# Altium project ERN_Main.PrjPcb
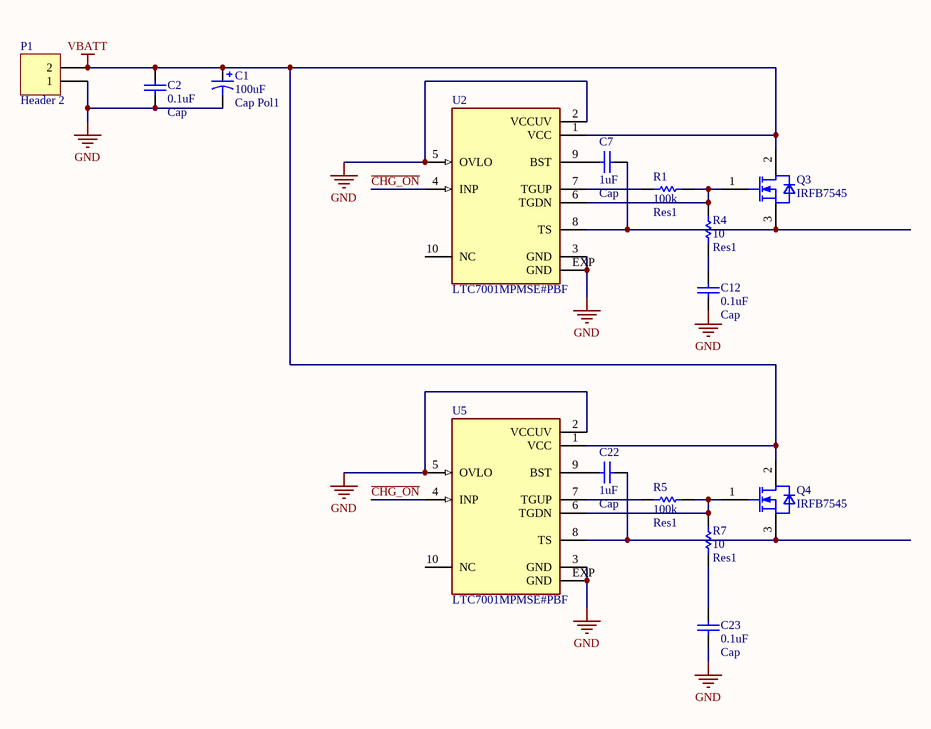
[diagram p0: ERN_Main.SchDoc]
4 sheets, 85 parts. Net scope: global (net labels, ports and power ports of the same name join across sheets).
Sheets:
  ERN_Main.SchDoc
  ERN_Main_2.SchDoc
  ERN_Main_3.SchDoc
  ERN_Main_4.SchDoc

## Sheet ERN_Main.SchDoc
size A; SheetNumber: 1; SheetTotal: 4; SPICEModelCacheDBTNACQE: <root> / <DocumentId>DBTNACQE</DocumentId> / </root>

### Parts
C1  Cap Pol1  value 100uF  [RB7.6-15]
C2  Cap  value 0.1uF  [RAD-0.3]
C7  Cap  value 1uF  [RAD-0.3]
C12  Cap  value 0.1uF  [RAD-0.3]
C22  Cap  value 1uF  [RAD-0.3]
C23  Cap  value 0.1uF  [RAD-0.3]
P1  Header 2  [HDR1X2]
Q3  IRFB7545  [IFX-PG-TO220-3-904]
Q4  IRFB7545  [IFX-PG-TO220-3-904]
R1  Res1  value 100k  [AXIAL-0.3]
R4  Res1  value 10  [AXIAL-0.3]
R5  Res1  value 100k  [AXIAL-0.3]
R7  Res1  value 10  [AXIAL-0.3]
U2  LTC7001MPMSE#PBF  [SOP50P490X110-11N]
U5  LTC7001MPMSE#PBF  [SOP50P490X110-11N]

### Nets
GND: C1.2 C2.1 C12.2 C23.2 P1.1 U2.2(VCCUV) U2.3(GND) U2.5(OVLO) U2.EXP(GND) U5.2(VCCUV) U5.3(GND) U5.5(OVLO) U5.EXP(GND)
VBATT: C1.1 C2.2 P1.2 Q3.2(DRAIN) Q4.2(DRAIN) U2.1(VCC) U5.1(VCC)
~{CHG_ON}: U2.4(INP) U5.4(INP)
NetC7_1: C7.1 Q3.3(SOURCE) U2.8(TS)
NetC7_2: C7.2 U2.9(BST)
NetC12_1: C12.1 R4.2
NetC22_1: C22.1 Q4.3(SOURCE) U5.8(TS)
NetC22_2: C22.2 U5.9(BST)
NetC23_1: C23.1 R7.2
NetQ3_1: Q3.1(GATE) R1.1 R4.1 U2.6(TGDN)
NetQ4_1: Q4.1(GATE) R5.1 R7.1 U5.6(TGDN)
NetR1_2: R1.2 U2.7(TGUP)
NetR5_2: R5.2 U5.7(TGUP)

Not connected (* = marked no-connect by the designer): U2 10(NC); U5 10(NC)

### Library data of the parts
C1 = Cap Pol1: Polarized Capacitor (Radial)
C2 C7 C12 C22 C23 = Cap: Capacitor
P1 = Header 2: Header, 2-Pin
Q3 Q4 = IRFB7545: N-Channel 60V 95A; Insulated-Gate Field-Effect Transistor (IGFET), N-Channel, Enhancement, Body Diode, Pin 1 Gate, 2 Drain, 3 Source, 3 Pins; Manufacturer: Infineon Technologies
R1 R4 R5 R7 = Res1: Resistor
U2 U5 = LTC7001MPMSE#PBF: Fast 150V High Side NMOS Static Switch Driver; MF: Analog Devices

## Sheet ERN_Main_2.SchDoc
size A; SheetNumber: 2; SheetTotal: 4; SPICEModelCacheYVUKJMZF: <root> / <DocumentId>YVUKJMZF</DocumentId> / <CacheFrame Number="0"> / <Model Name="1n5400" Kind="MDL"> / <Text>*1N5400 MCE / * 50V 3A Si Rectifier pkg:DO-201 1,2 / .MODEL 1N5400 D(IS=2.68E-12 RS=0.00977 N=1.17 TT=1.44E-5 CJO=1.24E-10 / + VJ=0.6 M=0.333 BV=66.6 IBV=1E-5 )</Text> / </Model> / <Model Name="led2" Kind="MDL"> / <Text>*Typ RED,GREEN,YELLOW,AMBER GaAs LED: Vf=2.1V Vr=4V If=40mA trr=3uS / *LED Pinout: 1=A, 2=K / .MODEL LED2 D (IS=93.1P RS=42M N=4.61 BV=4 IBV=10U / + CJO=2.97P VJ=.75 M=.333 TT=4.32U)</Text> / </Model> / </CacheFrame> / </root>
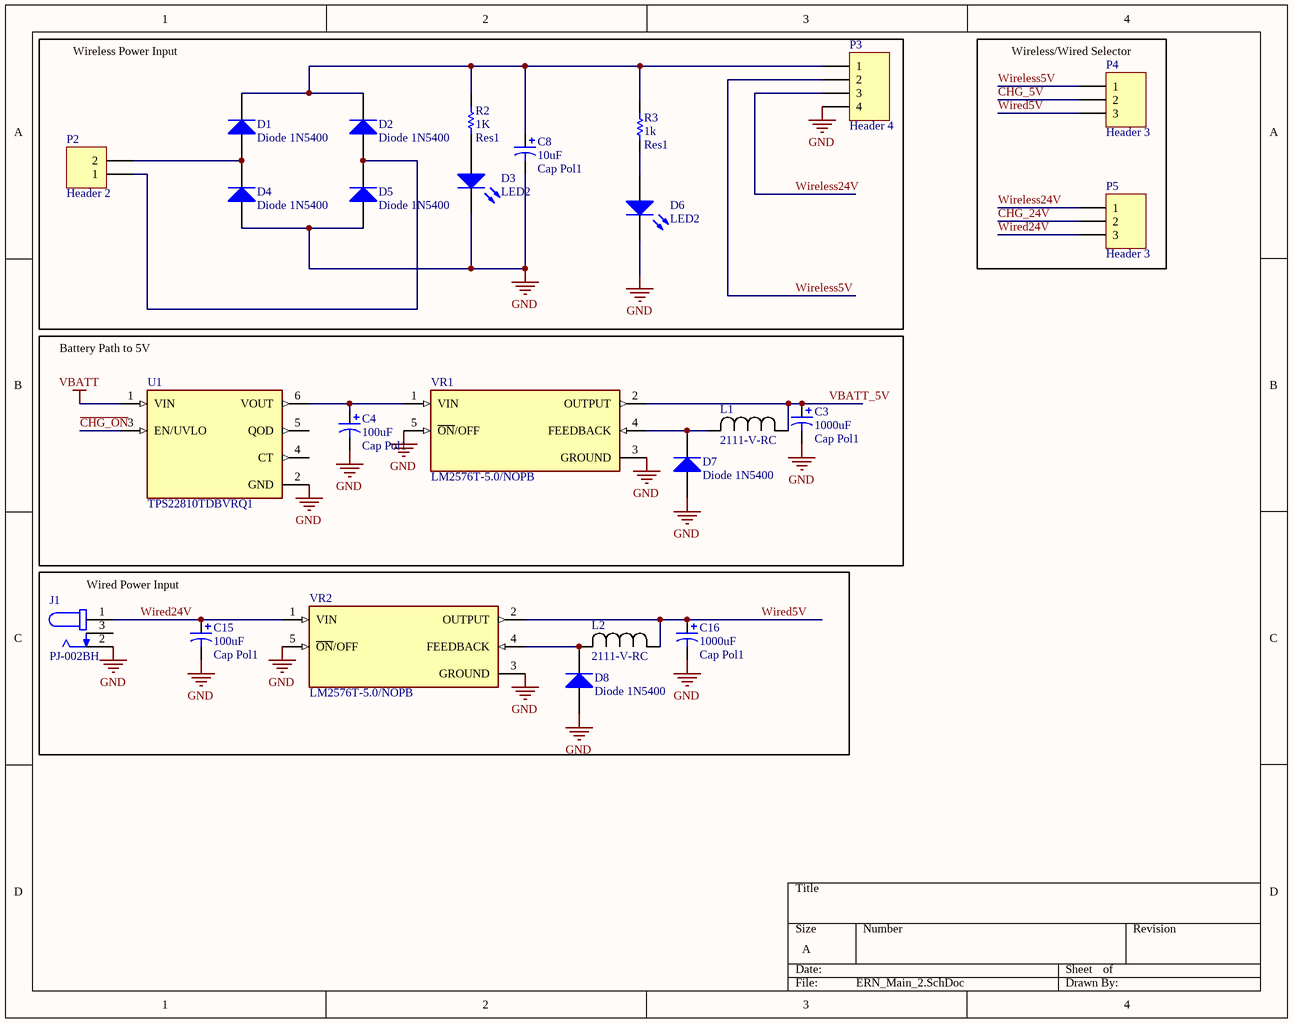
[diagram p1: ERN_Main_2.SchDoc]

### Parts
C3  Cap Pol1  value 1000uF  [RB7.6-15]
C4  Cap Pol1  value 100uF  [RB7.6-15]
C8  Cap Pol1  value 10uF  [RB7.6-15]
C15  Cap Pol1  value 100uF  [RB7.6-15]
C16  Cap Pol1  value 1000uF  [RB7.6-15]
D1  Diode 1N5400  [DO-201AD]
D2  Diode 1N5400  [DO-201AD]
D3  LED2  [3.2X1.6X1.1]
D4  Diode 1N5400  [DO-201AD]
D5  Diode 1N5400  [DO-201AD]
D6  LED2  [3.2X1.6X1.1]
D7  Diode 1N5400  [DO-201AD]
D8  Diode 1N5400  [DO-201AD]
J1  PJ-002BH  [CUI_PJ-002BH]
L1  2111-V-RC  [IND_21XX_27A_V]
L2  2111-V-RC  [IND_21XX_27A_V]
P2  Header 2  [HDR1X2]
P3  Header 4  [HDR1X4]
P4  Header 3  [HDR1X3]
P5  Header 3  [HDR1X3]
R2  Res1  value 1K  [AXIAL-0.3]
R3  Res1  value 1k  [AXIAL-0.3]
U1  TPS22810TDBVRQ1  [SOT95P280X145-6N]
VR1  LM2576T-5.0/NOPB  [TO170P1067X483X1651-5]
VR2  LM2576T-5.0/NOPB  [TO170P1067X483X1651-5]

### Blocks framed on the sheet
Wireless Power Input: C8 D1-D6 P2 P3 R2 R3
Wireless/Wired Selector: P4 P5
Battery Path to 5V: C3 C4 D7 L1 U1 VR1
Wired Power Input: C15 C16 D8 J1 L2 VR2

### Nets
GND: C3.2 C4.2 C8.2 C15.2 C16.2 D3.2(K) D4.1(A) D5.1(A) D6.2(K) D7.1(A) D8.1(A) J1.2 P3.4 U1.2(GND) VR1.3(GROUND) VR1.5(~{ON}/OFF) VR2.3(GROUND) VR2.5(~{ON}/OFF)
VBATT: U1.1(VIN)
~{CHG_ON}: U1.3(EN/UVLO)
CHG_5V: P4.2
CHG_24V: P5.2
VBATT_5V: C3.1 L1.1 VR1.2(OUTPUT)
Wired5V: C16.1 L2.1 P4.3 VR2.2(OUTPUT)
Wired24V: C15.1 J1.1 P5.3 VR2.1(VIN)
Wireless5V: P3.2 P4.1
Wireless24V: P3.3 P5.1
NetC4_1: C4.1 U1.6(VOUT) VR1.1(VIN)
NetC8_1: C8.1 D1.2(K) D2.2(K) P3.1 R2.2 R3.2
NetD1_1: D1.1(A) D4.2(K) P2.2
NetD2_1: D2.1(A) D5.2(K) P2.1
NetD3_1: D3.1(A) R2.1
NetD6_1: D6.1(A) R3.1
NetD7_2: D7.2(K) L1.2 VR1.4(FEEDBACK)
NetD8_2: D8.2(K) L2.2 VR2.4(FEEDBACK)

Not connected (* = marked no-connect by the designer): J1 3; U1 4(CT) 5(QOD)

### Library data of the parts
C3 C4 C8 C15 C16 = Cap Pol1: Polarized Capacitor (Radial)
D1 D2 D4 D5 D7 D8 = Diode 1N5400: 3 Amp General Purpose Rectifier
D3 D6 = LED2: Typical RED, GREEN, YELLOW, AMBER GaAs LED
J1 = PJ-002BH: 2.5 x 6.5 mm, 5.0 A, Horizontal, Through Hole, Dc Power Jack Connector; MF: Same Sky
L1 L2 = 2111-V-RC: Inductor 68uH; Manufacturer_Name: Bourns Electronics
P2 = Header 2: Header, 2-Pin
P3 = Header 4: Header, 4-Pin
P4 P5 = Header 3: Header, 3-Pin
R2 R3 = Res1: Resistor
U1 = TPS22810TDBVRQ1: Automotive 1-channel, 18-V, 2-A, 79-mâ„¦ load switch with adj. rise time and adj. output discharge; MF: Texas Instruments
VR1 VR2 = LM2576T-5.0/NOPB: SIMPLE SWITCHERÂ® 40V, 3A Low Component Count Step-Down Regulator; MF: Texas Instruments

## Sheet ERN_Main_3.SchDoc
size A; SheetNumber: 3; SheetTotal: 4; SPICEModelCacheXVWYUVSQ: <root> / <DocumentId>XVWYUVSQ</DocumentId> / <CacheFrame Number="0"> / <Model Name="irf1010" Kind="CKT"> / <Text>*IRF1010 MCE 4-2-96 / *55V  75A .014 ohm HEXFET pkg:TO-220 2,1,3 / .SUBCKT IRF1010  10 20 40 40 / M1   1  2  3  3  DMOS L=1U W=1U / RD  10  1  5.65M / RS  30  3  1.35M / RG  20  2  12.1 / CGS  2  3  2.15N / EGD 12  0  2  1  1 / VFB 14  0  0 / FFB  2  1  VFB  1 / CGD 13 14  4.49N / R1  13  0  1 / D1  12 13  DLIM / DDG 15 14  DCGD / R2  12 15  1 / D2  15  0  DLIM / DSD  3 10  DSUB / LS  30 40  7.5N / .MODEL DMOS NMOS (LEVEL=3 THETA=60M VMAX=114K ETA=2M VTO=3 KP=19.4) / .MODEL DCGD D (CJO=4.49N VJ=.6 M=.68) / .MODEL DSUB D (IS=311N N=1.5 RS=8.67M BV=55 CJO=4.08N VJ=.8 M=.42 TT=100N) / .MODEL DLIM D (IS=100U) / .ENDS IRF1010</Text> / </Model> / <Model Name="1n4148" Kind="MDL"> / <Text>.model 1N4148  D(Is=0.1p Rs=16 CJO=2p Tt=12n Bv=100 Ibv=0.1p)</Text> / </Model> / <Model Name="npn" Kind="MDL"> / <Text>*Default NPN BJT / *NPN Trans Pinout: C,B,E / .MODEL NPN NPN()</Text> / </Model> / </CacheFrame> / </root>
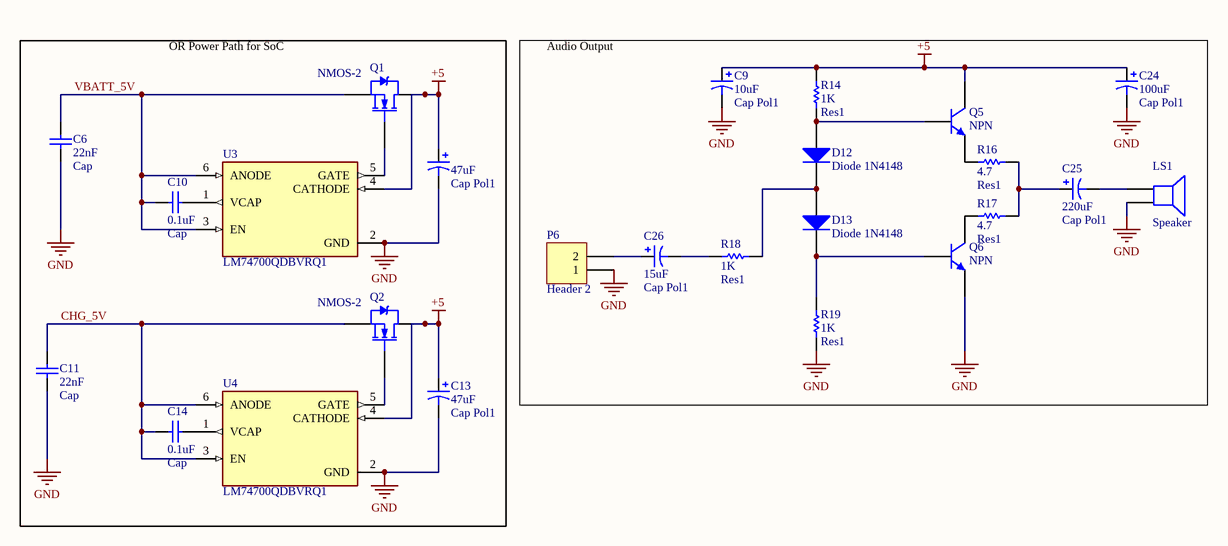
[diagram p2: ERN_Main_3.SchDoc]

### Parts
?  Cap Pol1  value 47uF  [RB7.6-15]
C6  Cap  value 22nF  [RAD-0.3]
C9  Cap Pol1  value 10uF  [RB7.6-15]
C10  Cap  value 0.1uF  [RAD-0.3]
C11  Cap  value 22nF  [RAD-0.3]
C13  Cap Pol1  value 47uF  [RB7.6-15]
C14  Cap  value 0.1uF  [RAD-0.3]
C24  Cap Pol1  value 100uF  [RB7.6-15]
C25  Cap Pol1  value 220uF  [RB7.6-15]
C26  Cap Pol1  value 15uF  [RB7.6-15]
D12  Diode 1N4148  [DO-35]
D13  Diode 1N4148  [DO-35]
LS1  Speaker  [PIN2]
P6  Header 2  [HDR1X2]
Q1  NMOS-2  [TO-220AB]
Q2  NMOS-2  [TO-220AB]
Q5  NPN  [TO-226-AA]
Q6  NPN  [TO-226-AA]
R14  Res1  value 1K  [AXIAL-0.3]
R16  Res1  value 4.7  [AXIAL-0.3]
R17  Res1  value 4.7  [AXIAL-0.3]
R18  Res1  value 1K  [AXIAL-0.3]
R19  Res1  value 1K  [AXIAL-0.3]
U3  LM74700QDBVRQ1  [SOT95P280X145-6N]
U4  LM74700QDBVRQ1  [SOT95P280X145-6N]

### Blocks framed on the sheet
OR Power Path for SoC: ? C6 C10 C11 C13 C14 Q1 Q2 U3 U4
Audio Output: C9 C24-C26 D12 D13 LS1 P6 Q5 Q6 R14 R16-R19

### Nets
+5: ?.1 C9.1 C13.1 C24.1 Q1.2(D) Q2.2(D) Q5.1(C) R14.2 U3.4(CATHODE) U4.4(CATHODE)
GND: ?.2 C6.1 C9.2 C11.1 C13.2 C24.2 LS1.2 P6.1 Q6.3(E) R19.1 U3.2(GND) U4.2(GND)
CHG_5V: C11.2 C14.2 Q2.3(S) U4.3(EN) U4.6(ANODE)
VBATT_5V: C6.2 C10.2 Q1.3(S) U3.3(EN) U3.6(ANODE)
NetC10_1: C10.1 U3.1(VCAP)
NetC14_1: C14.1 U4.1(VCAP)
NetC25_1: C25.1 R16.2 R17.2
NetC25_2: C25.2 LS1.1
NetC26_1: C26.1 P6.2
NetC26_2: C26.2 R18.1
NetD12_1: D12.1(A) Q5.2(B) R14.1
NetD12_2: D12.2(K) D13.1(A) R18.2
NetD13_2: D13.2(K) Q6.2(B) R19.2
NetQ1_1: Q1.1(G) U3.5(GATE)
NetQ2_1: Q2.1(G) U4.5(GATE)
NetQ5_3: Q5.3(E) R16.1
NetQ6_1: Q6.1(C) R17.1

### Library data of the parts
? C9 C13 C24-C26 = Cap Pol1: Polarized Capacitor (Radial)
C6 C10 C11 C14 = Cap: Capacitor
D12 D13 = Diode 1N4148: High Conductance Fast Diode
LS1 = Speaker: Loudspeaker
P6 = Header 2: Header, 2-Pin
Q1 Q2 = NMOS-2: N-Channel Power MOSFET; Note: Pin 2 is electrically connected to pin 4.
Q5 Q6 = NPN: NPN Bipolar Transistor
R14 R16-R19 = Res1: Resistor
U3 U4 = LM74700QDBVRQ1: 3.2-V to 65-V, 80-uA IQ automotive ideal diode controller; MF: Texas Instruments

## Sheet ERN_Main_4.SchDoc
size A; SheetNumber: 4; SheetTotal: 4; SPICEModelCacheELVNKBHK: <root> / <DocumentId>ELVNKBHK</DocumentId> / <CacheFrame Number="0"> / <Model Name="led2" Kind="MDL"> / <Text>*Typ RED,GREEN,YELLOW,AMBER GaAs LED: Vf=2.1V Vr=4V If=40mA trr=3uS / *LED Pinout: 1=A, 2=K / .MODEL LED2 D (IS=93.1P RS=42M N=4.61 BV=4 IBV=10U / + CJO=2.97P VJ=.75 M=.333 TT=4.32U)</Text> / </Model> / <Model Name="1n5400" Kind="MDL"> / <Text>*1N5400 MCE / * 50V 3A Si Rectifier pkg:DO-201 1,2 / .MODEL 1N5400 D(IS=2.68E-12 RS=0.00977 N=1.17 TT=1.44E-5 CJO=1.24E-10 / + VJ=0.6 M=0.333 BV=66.6 IBV=1E-5 )</Text> / </Model> / </CacheFrame> / </root>
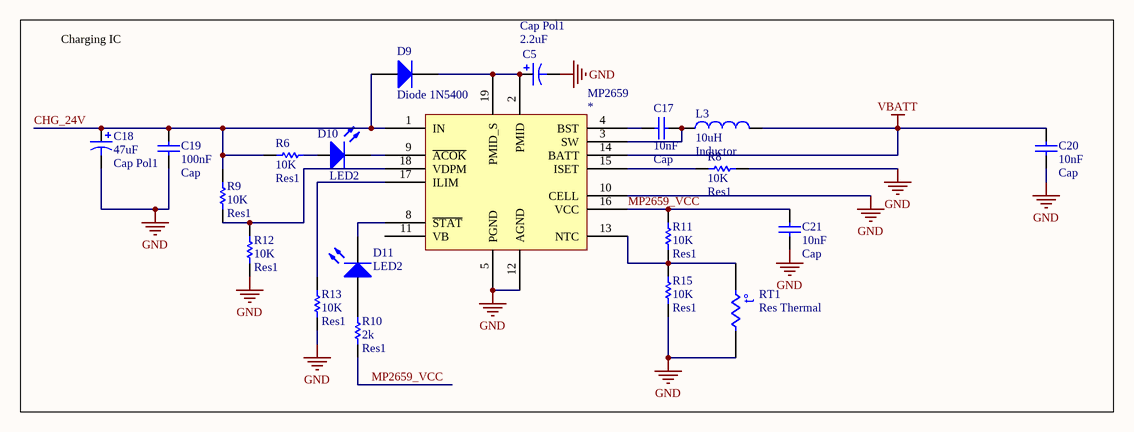
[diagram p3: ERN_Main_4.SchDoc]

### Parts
*  MP2659
C5  Cap Pol1  value 2.2uF  [RB7.6-15]
C17  Cap  value 10nF  [RAD-0.3]
C18  Cap Pol1  value 47uF  [RB7.6-15]
C19  Cap  value 100nF  [RAD-0.3]
C20  Cap  value 10nF  [RAD-0.3]
C21  Cap  value 10nF  [RAD-0.3]
D9  Diode 1N5400  [DO-201AD]
D10  LED2  [3.2X1.6X1.1]
D11  LED2  [3.2X1.6X1.1]
L3  Inductor  value 10uH  [0402-A]
R6  Res1  value 10K  [AXIAL-0.3]
R8  Res1  value 10K  [AXIAL-0.3]
R9  Res1  value 10K  [AXIAL-0.3]
R10  Res1  value 2k  [AXIAL-0.3]
R11  Res1  value 10K  [AXIAL-0.3]
R12  Res1  value 10K  [AXIAL-0.3]
R13  Res1  value 10K  [AXIAL-0.3]
R15  Res1  value 10K  [AXIAL-0.3]
RT1  Res Thermal  [6-0805_N]

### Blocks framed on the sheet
Charging IC: * C5 C17-C21 D9-D11 L3 R6 R8-R13 R15 RT1

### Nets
GND: *.5(PGND) *.10(CELL) *.12(AGND) C5.2 C18.2 C19.1 C20.2 C21.2 R8.2 R12.2 R13.2 R15.1 RT1.2
VBATT: *.14(BATT) C20.1 L3.2
CHG_24V: *.1(IN) C18.1 C19.2 D9.1(A) R6.2 R9.1
MP2659_VCC: *.16(VCC) C21.1 R10.2 R11.2
Net*_2: *.2(PMID) *.19(PMID_S) C5.1 D9.2(K)
Net*_3: *.3(SW) C17.1 L3.1
Net*_4: *.4(BST) C17.2
Net*_8: *.8(~{STAT}) D11.2(K)
Net*_9: *.9(~{ACOK}) D10.2(K)
Net*_13: *.13(NTC) R11.1 R15.2 RT1.1
Net*_15: *.15(ISET) R8.1
Net*_17: *.17(ILIM) R13.1
Net*_18: *.18(VDPM) R9.2 R12.1
NetD10_1: D10.1(A) R6.1
NetD11_1: D11.1(A) R10.1

Not connected (* = marked no-connect by the designer): * 11(VB)

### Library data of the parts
* = MP2659: 3S-6S Standalone Switching Charger
C5 C18 = Cap Pol1: Polarized Capacitor (Radial)
C17 C19-C21 = Cap: Capacitor
D9 = Diode 1N5400: 3 Amp General Purpose Rectifier
D10 D11 = LED2: as D3 on sheet ERN_Main_2
L3 = Inductor: Code_IEC: 1005
R6 R8-R13 R15 = Res1: Resistor
RT1 = Res Thermal: Thermistor

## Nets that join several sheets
GND: ERN_Main (13 pins), ERN_Main_2 (18 pins), ERN_Main_3 (12 pins), ERN_Main_4 (13 pins)
VBATT: ERN_Main (7 pins), ERN_Main_2 (U1.1), ERN_Main_4 (*.14 C20.1 L3.2)
~{CHG_ON}: ERN_Main (U2.4 U5.4), ERN_Main_2 (U1.3)
CHG_5V: ERN_Main_2 (P4.2), ERN_Main_3 (5 pins)
CHG_24V: ERN_Main_2 (P5.2), ERN_Main_4 (6 pins)
VBATT_5V: ERN_Main_2 (C3.1 L1.1 VR1.2), ERN_Main_3 (5 pins)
